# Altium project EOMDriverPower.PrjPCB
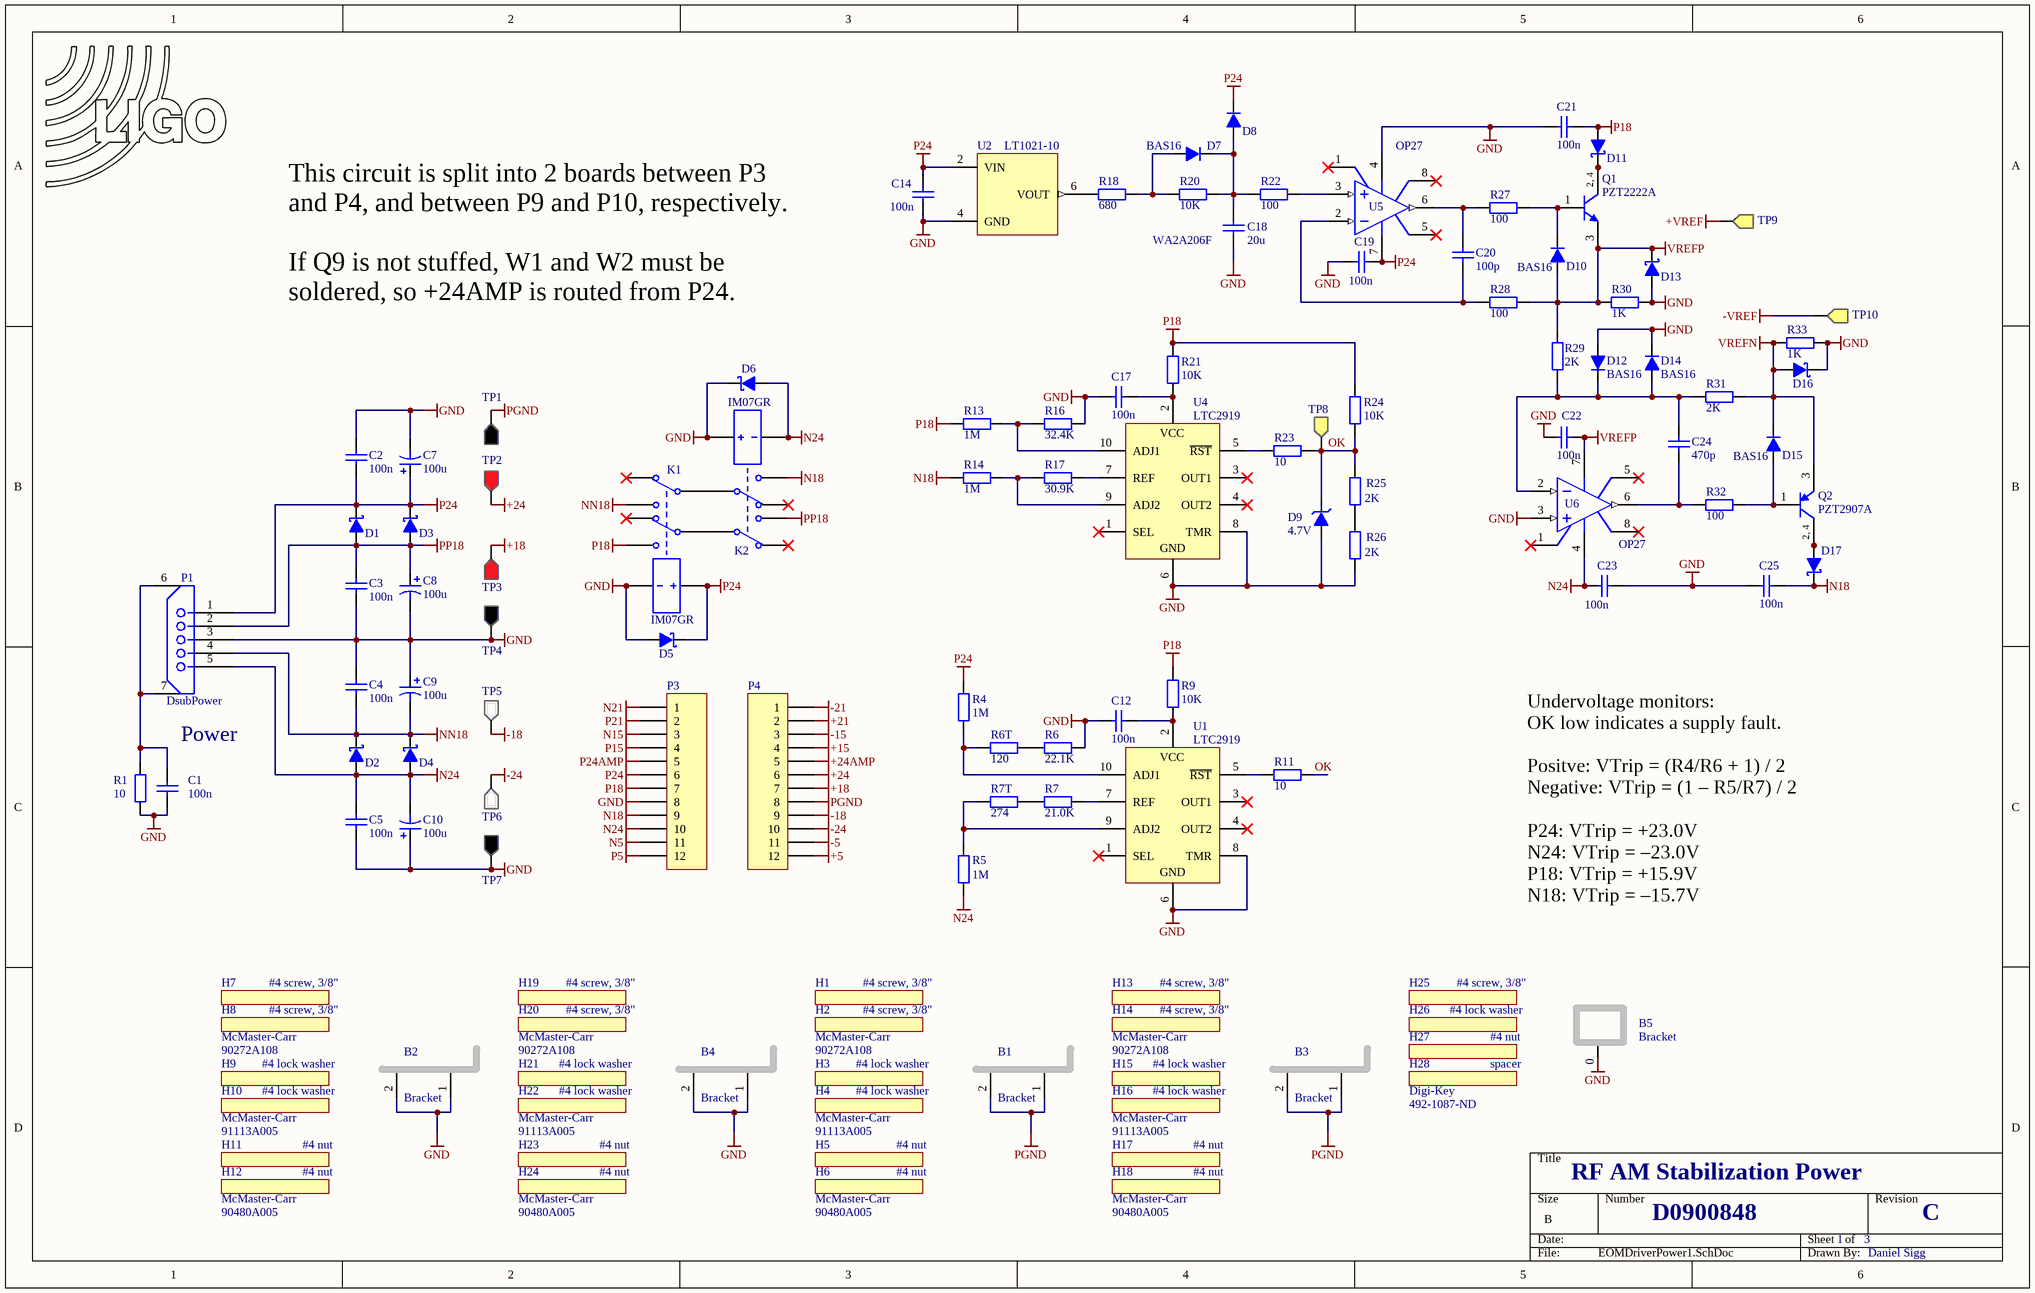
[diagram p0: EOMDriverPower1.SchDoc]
Title: D0900848
3 sheets, 330 parts. Net scope: global (net labels, ports and power ports of the same name join across sheets).
Board file: EOMDriverPower.PcbDoc
Sheets:
  EOMDriverPower1.SchDoc
  EOMDriverPower2.SchDoc
  EOMDriverPower3.SchDoc

## Sheet EOMDriverPower1.SchDoc: D0900848
size B; Engineer: Daniel Sigg; Revision: B; PageSetup: Record=PageOptions¦CenterHorizontal=True¦CenterVertical=True¦PrintScale=1.12¦XCorrection=1.00¦YCorrection=1.00¦PrintKind=0¦BorderSize=5000000¦LeftOffset=0¦BottomOffset=0¦Orientation=2¦PaperLength=1000¦PaperWidth=1000¦Scale=100¦PaperSource=7¦PrintQuality=-3¦MediaType=1¦DitherType=10¦PrintScaleMode=1¦PaperKind=11 x 17¦PaperIndex=121

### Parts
(Parts that share a designator on the sheet are numbered #1, #2 ... from top to bottom, then left to right.)
B1  Bracket  [Bracket-RA_708]
B2  Bracket  [Bracket-RA_708]
B3  Bracket  [Bracket-RA_708]
B4  Bracket  [Bracket-RA_708]
B5  Bracket  [Bracket-RA_7774]  (mechanical)
C1  100n  [CC2013-0805]
C2  100n  [CC2013-0805]
C3  100n  [CC2013-0805]
C4  100n  [CC2013-0805]
C5  100n  [CC2013-0805]
C7  100u  [AC103-041/G]
C8  100u  [AC103-041/G]
C9  100u  [AC103-041/G]
C10  100u  [AC103-041/G]
C12  100n  [CC2013-0805]
C14  100n  [CC2013-0805]
C17  100n  [CC2013-0805]
C18  Part Number: WA2A206F  [CA-ALL8]  (hidden comment: 20u)
C19  100n  [CC2013-0805]
C20  100p  [CC2013-0805]
C21  100n  [CC2013-0805]
C22  100n  [CC2013-0805]
C23  100n  [CC2013-0805]
C24  470p  [CC2013-0805]
C25  100n  [CC2013-0805]
D1  shottky diode  [DO-SMA]  (value not drawn)
D2  shottky diode  [DO-SMA]  (value not drawn)
D3  shottky diode  [DO-SMA]  (value not drawn)
D4  shottky diode  [DO-SMA]  (value not drawn)
D5  shottky diode  [DO-SMA]  (value not drawn)
D6  shottky diode  [DO-SMA]  (value not drawn)
D7  BAS16  [SO-G3/C2.25]
D8  BAS16  [SO-G3/C2.25]  (value not drawn)
D9  Voltage Rating: 4.7V  [DO-SOD123]  (hidden comment: zener diode)
D10  BAS16  [SO-G3/C2.25]
D11  shottky diode  [DO-SMA]  (value not drawn)
D12  BAS16  [SO-G3/C2.25]
D13  shottky diode  [DO-SMA]  (value not drawn)
D14  BAS16  [SO-G3/C2.25]
D15  BAS16  [SO-G3/C2.25]
D16  shottky diode  [DO-SMA]  (value not drawn)
D17  shottky diode  [DO-SMA]  (value not drawn)
H1  #4 screw, 3/8"  (mechanical)
H2  #4 screw, 3/8"  Part Number: 90272A108  Distributor: McMaster-Carr  (mechanical)
H3  #4 lock washer  (mechanical)
H4  #4 lock washer  Part Number: 91113A005  Distributor: McMaster-Carr  (mechanical)
H5  #4 nut  (mechanical)
H6  #4 nut  Part Number: 90480A005  Distributor: McMaster-Carr  (mechanical)
H7  #4 screw, 3/8"  (mechanical)
H8  #4 screw, 3/8"  Part Number: 90272A108  Distributor: McMaster-Carr  (mechanical)
H9  #4 lock washer  (mechanical)
H10  #4 lock washer  Part Number: 91113A005  Distributor: McMaster-Carr  (mechanical)
H11  #4 nut  (mechanical)
H12  #4 nut  Part Number: 90480A005  Distributor: McMaster-Carr  (mechanical)
H13  #4 screw, 3/8"  (mechanical)
H14  #4 screw, 3/8"  Part Number: 90272A108  Distributor: McMaster-Carr  (mechanical)
H15  #4 lock washer  (mechanical)
H16  #4 lock washer  Part Number: 91113A005  Distributor: McMaster-Carr  (mechanical)
H17  #4 nut  (mechanical)
H18  #4 nut  Part Number: 90480A005  Distributor: McMaster-Carr  (mechanical)
H19  #4 screw, 3/8"  (mechanical)
H20  #4 screw, 3/8"  Part Number: 90272A108  Distributor: McMaster-Carr  (mechanical)
H21  #4 lock washer  (mechanical)
H22  #4 lock washer  Part Number: 91113A005  Distributor: McMaster-Carr  (mechanical)
H23  #4 nut  (mechanical)
H24  #4 nut  Part Number: 90480A005  Distributor: McMaster-Carr  (mechanical)
H25  #4 screw, 3/8"  (mechanical)
H26  #4 lock washer  (mechanical)
H27  #4 nut  (mechanical)
H28  spacer  Part Number: 492-1087-ND  Distributor: Digi-Key  (mechanical)
K1  IM07GR  [RELAY_IMG]
K2  IM07GR  [RELAY_IMG]
LOGO1#1  LIGO logo  [LIGO_LOGO]  (value not drawn)  (no BOM)
P1  DsubPower  [DSUB-PWR5-RAPLUG]
P3  TBlock_5.08_12  [TBLOCK-5.08-12]  (value not drawn)
P4  TBlock_5.08_12  [TBLOCK-5.08-12]  (value not drawn)
Q1  PZT2222A  [SOT223]
Q2  PZT2907A  [SOT223]
R1  10  [CR2012-0805]
R4  1M  [CR2012-0805]
R5  1M  [CR2012-0805]
R6  22.1K  [CR2012-0805]
R6T  120  [CR2012-0805]
R7  21.0K  [CR2012-0805]
R7T  274  [CR2012-0805]
R9  10K  [CR2012-0805]
R11  10  [CR2012-0805]
R13  1M  [CR2012-0805]
R14  1M  [CR2012-0805]
R16  32.4K  [CR2012-0805]
R17  30.9K  [CR2012-0805]
R18  680  [CR2012-0805]
R20  10K  [CR2012-0805]
R21  10K  [CR2012-0805]
R22  100  [CR2012-0805]
R23  10  [CR2012-0805]
R24  10K  [CR2012-0805]
R25  2K  [CR2012-0805]
R26  2K  [CR2012-0805]
R27  100  [CR2012-0805]
R28  100  [CR2012-0805]
R29  2K  [CR2012-0805]
R30  1K  [CR2012-0805]
R31  2K  [CR2012-0805]
R32  100  [CR2012-0805]
R33  1K  [CR2012-0805]
TP1  Testpoint  [TP1]  (value not drawn)
TP2  Testpoint  [TP1]  (value not drawn)
TP3  Testpoint  [TP1]  (value not drawn)
TP4  Testpoint  [TP1]  (value not drawn)
TP5  Testpoint  [TP1]  (value not drawn)
TP6  Testpoint  [TP1]  (value not drawn)
TP7  Testpoint  [TP1]  (value not drawn)
TP8  Testpoint  [TP1]  (value not drawn)
TP9  Testpoint  [TP1]  (value not drawn)
TP10  Testpoint  [TP1]  (value not drawn)
U1  LTC2919  [MSOP10]
U2  LT1021-10  [DIP-8]
U4  LTC2919  [MSOP10]
U5  OP27  [SO-G8]
U6  OP27  [SO-G8]

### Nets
+5: P4.12
+15: P4.4
+18: P4.7 TP3.1
+21: P4.2
+24: P4.6 TP2.1
+24AMP: P4.5
+VREF: TP9.1
-5: P4.11
-15: P4.3
-18: P4.9 TP5.1
-21: P4.1
-24: P4.10 TP6.1
-VREF: TP10.1
GND: B2.1(GND) B2.2(GND) B4.1(GND) B4.2(GND) C1.2 C2.1 C3.1 C4.2 C5.2 C7.2 C8.2 C9.1 C10.1 C12.1 C14.1 C17.1 C18.2 C19.1 C21.2 C22.2 C23.1 C25.2 D5.1(A) D6.2(K) D9.1(A) D12.1(A) D13.1(A) D14.3(K) D16.2(K) K1.8(COIL2) K2.7(COIL1) P1.3(A3) P3.8 R1.2 R6.1 R16.1 R26.1 R30.2 R33.2 TP4.1 TP7.1 U1.6(GND) U1.8(TMR) U2.4(GND) U4.6(GND) U4.8(TMR) U5.4(V-) U6.3(IN+)
N5: P3.11
N15: P3.3
N18: C25.1 D17.2(K) K2.6(2NO) P3.9 R14.2
N21: P3.1
N24: C5.1 C10.2 C23.2 D2.1(A) D4.1(A) D6.1(A) K2.8(COIL2) P1.5(A5) P3.10 R5.2 U6.4(V-)
NN18: C4.1 C9.2 D2.2(K) D4.2(K) K1.3(1NO) P1.4(A4)
P5: P3.12
P15: P3.4
P18: C21.1 D11.1(A) K1.6(2NO) P3.7 R9.2 R13.2 R21.2 R24.2
P21: P3.2
P24: C2.2 C7.1 C14.2 C19.2 D1.2(K) D3.2(K) D5.2(K) D8.3(K) K1.7(COIL1) P1.1(A1) P3.6 R4.1 U2.2(VIN) U5.7(V+)
P24AMP: P3.5
PGND: B1.1(GND) B1.2(GND) B3.1(GND) B3.2(GND) P4.8 TP1.1
PP18: C3.2 C8.1 D1.1(A) D3.1(A) K2.3(1NO) P1.2(A2)
VREFN: D15.3(K) D16.1(A) Q2.3(E) R31.2 R33.1
VREFP: C22.1 D10.1(A) D13.2(K) Q1.3(E) R28.2 R29.1 R30.1 U6.7(V+)
OK: D9.2(K) R11.2 R23.2 R24.1 R25.2 TP8.1
NetC1_1: C1.1 P1.6(A6) P1.7(A7) R1.1
NetC12_2: C12.2 R9.1 U1.2(VCC)
NetC17_2: C17.2 R21.1 U4.2(VCC)
NetC18_1: C18.1 D7.3(K) D8.1(A) R20.2 R22.1
NetC20_1: C20.1 R28.1 U5.2(IN-)
NetC20_2: C20.2 R27.1 U5.6(OUT)
NetC24_1: C24.1 R32.2 U6.6(OUT)
NetC24_2: C24.2 D12.3(K) D14.1(A) R29.2 R31.1 U6.2(IN-)
NetD7_1: D7.1(A) R18.2 R20.1
NetD10_3: D10.3(K) Q1.1(B) R27.2
NetD11_2: D11.2(K) Q1.2(C) Q1.4(C)
NetD15_1: D15.1(A) Q2.1(B) R32.1
NetD17_1: D17.1(A) Q2.2(C) Q2.4(C)
NetK1_1: K1.1(1COM) K2.4(2COM)
NetK1_4: K1.4(2COM) K2.1(1COM)
NetR4_2: R4.2 R6T.2 U1.10(ADJ1)
NetR5_1: R5.1 R7T.2 U1.9(ADJ2)
NetR6_2: R6.2 R6T.1
NetR7_1: R7.1 U1.7(REF)
NetR7_2: R7.2 R7T.1
NetR11_1: R11.1 U1.5(~{RST})
NetR13_1: R13.1 R16.2 U4.10(ADJ1)
NetR14_1: R14.1 R17.2 U4.9(ADJ2)
NetR17_1: R17.1 U4.7(REF)
NetR18_1: R18.1 U2.6(VOUT)
NetR22_2: R22.2 U5.3(IN+)
NetR23_1: R23.1 U4.5(~{RST})
NetR25_1: R25.1 R26.2

Not connected (* = marked no-connect by the designer): B5 0(GND); D7 2; D8 2; D10 2; D12 2; D14 2; D15 2; K1 2(1NC)* 5(2NC)*; K2 2(1NC)* 5(2NC)*; U1 1(SEL)* 3(OUT1)* 4(OUT2)*; U2 1(DNC) 3(DNC) 5(DNC) 7(DNC) 8(DNC); U4 1(SEL)* 3(OUT1)* 4(OUT2)*; U5 1(CMPEN)* 5(NC)* 8(CMPEN)*; U6 1(CMPEN)* 5(NC)* 8(CMPEN)*

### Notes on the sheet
- This circuit is split into 2 boards between P3
  and P4, and between P9 and P10, respectively.
  If Q9 is not stuffed, W1 and W2 must be
  soldered, so +24AMP is routed from P24.
- Power
- Undervoltage monitors:
  OK low indicates a supply fault.
  Positve: VTrip = (R4/R6 + 1) / 2
  Negative: VTrip = (1 – R5/R7) / 2
  P24: VTrip = +23.0V
  N24: VTrip = –23.0V
  P18: VTrip = +15.9V
  N18: VTrip = –15.7V
- RF AM Stabilization Power
- D0900848
- 1
- 3
- C
- Daniel Sigg
- Labels drawn without touching a wire or pin: GND

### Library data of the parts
B1-B4 = Bracket_708: Keystone Electronics right-angle 6-32 steel, 708; Part Number: 708K-ND
B5 = Bracket_7774: Keystone Electronics right-angle 4-40 steel, 616; Part Number: 616K-ND
C1-C5 C12 C14 C17 C19 C21-C23 C25 = ChipCap: Capacitor, surface mount; Part Number: 311-1140-1-ND; Tolerance: 10%
C7-C10 = ChipElectrolyte: Electrolyte capacitor, surface mount; Part Number: PCE3819CT-ND; Tolerance: 20%; Voltage Rating: 63V
C18 = CapFilmAxial: Film Capacitor, axial lead; Tolerance: 1%; Voltage Rating: 50V
C20 = ChipCap: Capacitor, surface mount; Part Number: 311-1111-1-ND; Tolerance: 10%
C24 = ChipCap: Capacitor, surface mount; Part Number: 311-1119-1-ND; Tolerance: 10%
D1-D4 D11 D13 D16 D17 = DIODE_SHOTTKY: Single shottky diode; Part Number: 641-1258-1-ND; Voltage Rating: 40V
D5 D6 = DIODE_SHOTTKY: Single shottky diode; Part Number: 641-1258-1-ND
D7 D8 D10 D12 D14 D15 = DIODE_SOT23: Single diode in SOT23 package; Part Number: BAS16FSCT-ND
D9 = DIODE_ZENER: Single zener diode; Part Number: MMSZ5230B-FDICT-ND
H1 H7 H13 H19 H25 = Partlist: Mounting hardware; Part Number: 90272A108
H2 H4 H6 H8 H10 H12 H14 H16 H18 H20 H22 H24 = Partlist: Mounting hardware
H3 H9 H15 H21 H26 = Partlist: Mounting hardware; Part Number: 91113A005
H5 H11 H17 H23 H27 = Partlist: Mounting hardware; Part Number: 90480A005
H28 = Partlist: Spacer, 0.125", #4
K1 K2 = Relay_DPDT: Dual-pole dual-throw relay; Part Number: PB1090CT-ND; Coil Voltage: 24V; Current Rating: 2A
LOGO1#1 = LIGO_logo
P1 = DSUB_PWR_5PIN: 5 contact Dsub Power Connector; Part Number: 609-2834-ND
P3 = TBlock_5.08_12: Terminal block, 5.08mm, 12-Pin; Part Number: 281-1285-ND
P4 = TBlock_5.08_12: Terminal block, 5.08mm, 12-Pin; Part Number: NL
Q1 = PZTA42: NPN General Purpose Transistor; Part Number: PZT2222ACT-ND
Q2 = BCP51: PNP Medium Power Transistor; Part Number: PZT2907AT1GOSCT-ND
R1 R11 R23 = ChipRes1: Resistor, surface mount; Part Number: A103143CT-ND; Tolerance: 0.1%
R4 R5 R13 R14 = ChipRes1: Resistor, surface mount; Part Number: P1MDACT-ND; Tolerance: 0.1%
R6 = ChipRes1: Resistor, surface mount; Part Number: P22.1KDACT-ND; Tolerance: 0.1%
R6T = ChipRes1: Resistor, surface mount; Part Number: P120DACT-ND; Tolerance: 0.1%
R7 = ChipRes1: Resistor, surface mount; Part Number: P21KDACT-ND; Tolerance: 0.1%
R7T = ChipRes1: Resistor, surface mount; Part Number: P274DACT-ND; Tolerance: 0.1%
R9 R20 R21 R24 = ChipRes1: Resistor, surface mount; Part Number: P10KDACT-ND; Tolerance: 0.1%
R16 = ChipRes1: Resistor, surface mount; Part Number: P32.4KDACT-ND; Tolerance: 0.1%
R17 = ChipRes1: Resistor, surface mount; Part Number: P30.9KDACT-ND; Tolerance: 0.1%
R18 = ChipRes1: Resistor, surface mount; Part Number: P680DACT-ND; Tolerance: 0.1%
R22 R27 R28 R32 = ChipRes1: Resistor, surface mount; Part Number: P100DACT-ND; Tolerance: 0.1%
R25 R26 R29 R31 = ChipRes1: Resistor, surface mount; Part Number: P2.0KDACT-ND; Tolerance: 0.1%
R30 R33 = ChipRes1: Resistor, surface mount; Part Number: P1.0KDACT-ND; Tolerance: 0.1%
TP1 TP4 TP7 = TP_GND: Testpoint, black; Part Number: 5006K-ND
TP2 TP3 = TP_POSITIVE: Testpoint, red; Part Number: 5005K-ND
TP5 TP6 = TP_NEGATIVE: Testpoint, white; Part Number: 5007K-ND
TP8-TP10 = TP_SIGNAL: Testpoint, yellow; Part Number: 5009K-ND
U1 U4 = LTC2919: Precision Triple/Dual Input UV, OV and Negative Voltage Monitor; Part Number: LTC2919CMS-5#PBF-ND
U2 = LT1021-7: Voltage Ref; Part Number: LT1021BCN8-10#PBF
U5 U6 = OP27GS: Low-Noise, Precision Operational Amplifier; Part Number: OP27GSZ-ND

## Sheet EOMDriverPower2.SchDoc: D0900848
size B
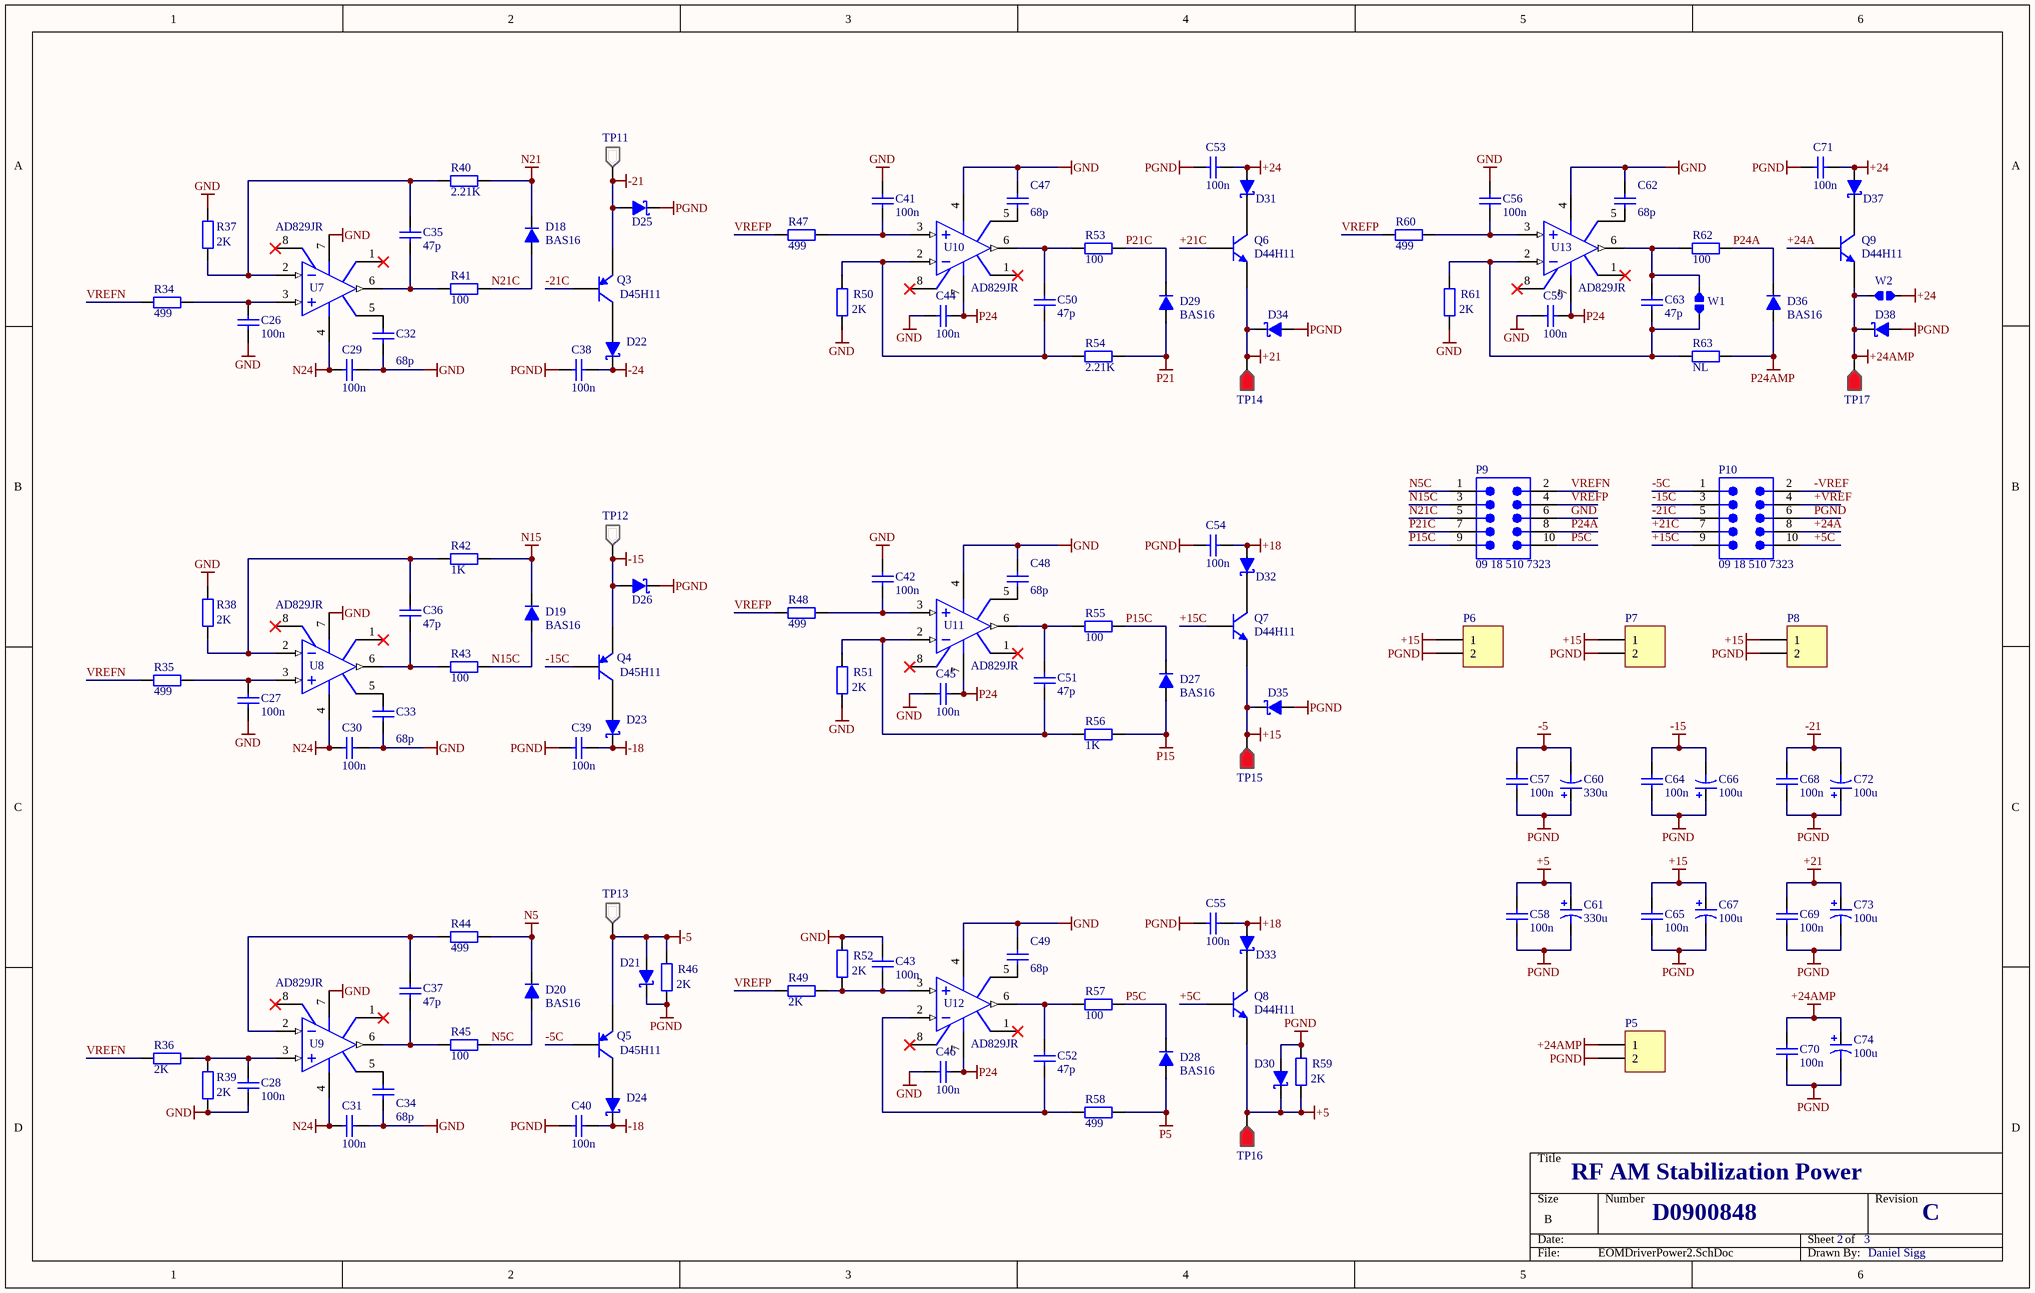
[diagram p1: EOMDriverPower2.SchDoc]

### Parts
C26  100n  [CC2013-0805]
C27  100n  [CC2013-0805]
C28  100n  [CC2013-0805]
C29  100n  [CC2013-0805]
C30  100n  [CC2013-0805]
C31  100n  [CC2013-0805]
C32  68p  [CC2013-0805]
C33  68p  [CC2013-0805]
C34  68p  [CC2013-0805]
C35  47p  [CC2013-0805]
C36  47p  [CC2013-0805]
C37  47p  [CC2013-0805]
C38  100n  [CC2013-0805]
C39  100n  [CC2013-0805]
C40  100n  [CC2013-0805]
C41  100n  [CC2013-0805]
C42  100n  [CC2013-0805]
C43  100n  [CC2013-0805]
C44  100n  [CC2013-0805]
C45  100n  [CC2013-0805]
C46  100n  [CC2013-0805]
C47  68p  [CC2013-0805]
C48  68p  [CC2013-0805]
C49  68p  [CC2013-0805]
C50  47p  [CC2013-0805]
C51  47p  [CC2013-0805]
C52  47p  [CC2013-0805]
C53  100n  [CC2013-0805]
C54  100n  [CC2013-0805]
C55  100n  [CC2013-0805]
C56  100n  [CC2013-0805]
C57  100n  [CC2013-0805]
C58  100n  [CC2013-0805]
C59  100n  [CC2013-0805]
C60  330u  [AC083-033/F]
C61  330u  [AC083-033/F]
C62  68p  [CC2013-0805]
C63  47p  [CC2013-0805]
C64  100n  [CC2013-0805]
C65  100n  [CC2013-0805]
C66  100u  [AC083-033/F]
C67  100u  [AC083-033/F]
C68  100n  [CC2013-0805]
C69  100n  [CC2013-0805]
C70  100n  [CC2013-0805]
C71  100n  [CC2013-0805]
C72  100u  [AC083-033/F]
C73  100u  [AC083-033/F]
C74  100u  [AC083-033/F]
D18  BAS16  [SO-G3/C2.25]
D19  BAS16  [SO-G3/C2.25]
D20  BAS16  [SO-G3/C2.25]
D21  shottky diode  [DO-SMA]  (value not drawn)
D22  shottky diode  [DO-SMA]  (value not drawn)
D23  shottky diode  [DO-SMA]  (value not drawn)
D24  shottky diode  [DO-SMA]  (value not drawn)
D25  shottky diode  [DO-SMA]  (value not drawn)
D26  shottky diode  [DO-SMA]  (value not drawn)
D27  BAS16  [SO-G3/C2.25]
D28  BAS16  [SO-G3/C2.25]
D29  BAS16  [SO-G3/C2.25]
D30  shottky diode  [DO-SMA]  (value not drawn)
D31  shottky diode  [DO-SMA]  (value not drawn)
D32  shottky diode  [DO-SMA]  (value not drawn)
D33  shottky diode  [DO-SMA]  (value not drawn)
D34  shottky diode  [DO-SMA]  (value not drawn)
D35  shottky diode  [DO-SMA]  (value not drawn)
D36  BAS16  [SO-G3/C2.25]
D37  shottky diode  [DO-SMA]  (value not drawn)
D38  shottky diode  [DO-SMA]  (value not drawn)
P5  TBlock_5.08_2  [TBLOCK-5.08-2]  (value not drawn)
P6  TBlock_5.08_2  [TBLOCK-5.08-2]  (value not drawn)
P7  TBlock_5.08_2  [TBLOCK-5.08-2]  (value not drawn)
P8  TBlock_5.08_2  [TBLOCK-5.08-2]  (value not drawn)
P9  09 18 510 7323  [918510x323]
P10  09 18 510 7323  [918510x324]
Q3  D45H11  [TO-220V]
Q4  D45H11  [TO-220V]
Q5  D45H11  [TO-220V]
Q6  D44H11  [TO-220V]
Q7  D44H11  [TO-220V]
Q8  D44H11  [TO-220V]
Q9  D44H11  [TO-220V]
R34  499  [CR2012-0805]
R35  499  [CR2012-0805]
R36  2K  [CR2012-0805]
R37  2K  [CR2012-0805]
R38  2K  [CR2012-0805]
R39  2K  [CR2012-0805]
R40  2.21K  [CR2012-0805]
R41  100  [CR2012-0805]
R42  1K  [CR2012-0805]
R43  100  [CR2012-0805]
R44  499  [CR2012-0805]
R45  100  [CR2012-0805]
R46  2K  [CR2012-0805]
R47  499  [CR2012-0805]
R48  499  [CR2012-0805]
R49  2K  [CR2012-0805]
R50  2K  [CR2012-0805]
R51  2K  [CR2012-0805]
R52  2K  [CR2012-0805]
R53  100  [CR2012-0805]
R54  2.21K  [CR2012-0805]
R55  100  [CR2012-0805]
R56  1K  [CR2012-0805]
R57  100  [CR2012-0805]
R58  499  [CR2012-0805]
R59  2K  [CR2012-0805]
R60  499  [CR2012-0805]
R61  2K  [CR2012-0805]
R62  100  [CR2012-0805]
R63  NL  [CR2012-0805]
TP11  Testpoint  [TP1]  (value not drawn)
TP12  Testpoint  [TP1]  (value not drawn)
TP13  Testpoint  [TP1]  (value not drawn)
TP14  Testpoint  [TP1]  (value not drawn)
TP15  Testpoint  [TP1]  (value not drawn)
TP16  Testpoint  [TP1]  (value not drawn)
TP17  Testpoint  [TP1]  (value not drawn)
U7  AD829JR  [SO-G8]
U8  AD829JR  [SO-G8]
U9  AD829JR  [SO-G8]
U10  AD829JR  [SO-G8]
U11  AD829JR  [SO-G8]
U12  AD829JR  [SO-G8]
U13  AD829JR  [SO-G8]
W1  Jumper  [JR2013-0805]  (value not drawn)  (no BOM)
W2  Jumper  [JR2013-0805]  (value not drawn)  (no BOM)

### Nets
+5: C58.2 C61.1 D30.2(K) Q8.3(E) R59.1 TP16.1
+15: C65.2 C67.1 D35.2(K) P6.1 P7.1 P8.1 Q7.3(E) TP15.1
+18: C54.1 C55.1 D32.1(A) D33.1(A)
+21: C69.2 C73.1 D34.2(K) Q6.3(E) TP14.1
+24: C53.1 C71.1 D31.1(A) D37.1(A) W2.1
+24AMP: C70.2 C74.1 D38.2(K) P5.1 Q9.3(E) TP17.1 W2.2
+VREF: P10.4
-5: C57.1 C60.2 D21.1(A) Q5.3(E) R46.2 TP13.1
-15: C64.1 C66.2 D26.1(A) Q4.3(E) TP12.1
-18: C39.1 C40.1 D23.2(K) D24.2(K)
-21: C68.1 C72.2 D25.1(A) Q3.3(E) TP11.1
-24: C38.1 D22.2(K)
-VREF: P10.2
GND: C26.1 C27.1 C28.1 C29.1 C30.1 C31.1 C32.1 C33.1 C34.1 C41.2 C42.2 C43.2 C44.2 C45.2 C46.2 C47.2 C48.2 C49.2 C56.2 C59.2 C62.2 P9.6 R37.1 R38.1 R39.2 R50.1 R51.1 R52.2 R61.1 U7.7(V+) U8.7(V+) U9.7(V+) U10.4(V-) U11.4(V-) U12.4(V-) U13.4(V-)
N5: D20.3(K) R44.1
N15: D19.3(K) R42.1
N21: D18.3(K) R40.1
N24: C29.2 C30.2 C31.2 U7.4(V-) U8.4(V-) U9.4(V-)
P5: D28.1(A) R58.2
P15: D27.1(A) R56.2
P21: D29.1(A) R54.2
P24: C44.1 C45.1 C46.1 C59.1 U10.7(V+) U11.7(V+) U12.7(V+) U13.7(V+)
P24AMP: D36.1(A) R63.2
PGND: C38.2 C39.2 C40.2 C53.2 C54.2 C55.2 C57.2 C58.1 C60.1 C61.2 C64.2 C65.1 C66.1 C67.2 C68.2 C69.1 C70.1 C71.2 C72.1 C73.2 C74.2 D21.2(K) D25.2(K) D26.2(K) D30.1(A) D34.1(A) D35.1(A) D38.1(A) P5.2 P6.2 P7.2 P8.2 P10.6 R46.1 R59.2
VREFN: P9.2 R34.1 R35.1 R36.1
VREFP: P9.4 R47.1 R48.1 R49.1 R60.1
+5C: P10.10 Q8.1(B)
+15C: P10.9 Q7.1(B)
+21C: P10.7 Q6.1(B)
+24A: P10.8 Q9.1(B)
-5C: P10.1 Q5.1(B)
-15C: P10.3 Q4.1(B)
-21C: P10.5 Q3.1(B)
N5C: D20.1(A) P9.1 R45.1
N15C: D19.1(A) P9.3 R43.1
N21C: D18.1(A) P9.5 R41.1
P5C: D28.3(K) P9.10 R57.2
P15C: D27.3(K) P9.9 R55.2
P21C: D29.3(K) P9.7 R53.2
P24A: D36.3(K) P9.8 R62.2
NetC26_2: C26.2 R34.2 U7.3(IN+)
NetC27_2: C27.2 R35.2 U8.3(IN+)
NetC28_2: C28.2 R36.2 R39.1 U9.3(IN+)
NetC32_2: C32.2 U7.5(C_COMP)
NetC33_2: C33.2 U8.5(C_COMP)
NetC34_2: C34.2 U9.5(C_COMP)
NetC35_1: C35.1 R41.2 U7.6(OUT)
NetC35_2: C35.2 R37.2 R40.2 U7.2(IN-)
NetC36_1: C36.1 R43.2 U8.6(OUT)
NetC36_2: C36.2 R38.2 R42.2 U8.2(IN-)
NetC37_1: C37.1 R45.2 U9.6(OUT)
NetC37_2: C37.2 R44.2 U9.2(IN-)
NetC41_1: C41.1 R47.2 U10.3(IN+)
NetC42_1: C42.1 R48.2 U11.3(IN+)
NetC43_1: C43.1 R49.2 R52.1 U12.3(IN+)
NetC47_1: C47.1 U10.5(C_COMP)
NetC48_1: C48.1 U11.5(C_COMP)
NetC49_1: C49.1 U12.5(C_COMP)
NetC50_1: C50.1 R50.2 R54.1 U10.2(IN-)
NetC50_2: C50.2 R53.1 U10.6(OUT)
NetC51_1: C51.1 R51.2 R56.1 U11.2(IN-)
NetC51_2: C51.2 R55.1 U11.6(OUT)
NetC52_1: C52.1 R58.1 U12.2(IN-)
NetC52_2: C52.2 R57.1 U12.6(OUT)
NetC56_1: C56.1 R60.2 U13.3(IN+)
NetC62_1: C62.1 U13.5(C_COMP)
NetC63_1: C63.1 R61.2 R63.1 U13.2(IN-) W1.1
NetC63_2: C63.2 R62.1 U13.6(OUT) W1.2
NetD22_1: D22.1(A) Q3.2(C)
NetD23_1: D23.1(A) Q4.2(C)
NetD24_1: D24.1(A) Q5.2(C)
NetD31_2: D31.2(K) Q6.2(C)
NetD32_2: D32.2(K) Q7.2(C)
NetD33_2: D33.2(K) Q8.2(C)
NetD37_2: D37.2(K) Q9.2(C)

Not connected (* = marked no-connect by the designer): D18 2; D19 2; D20 2; D27 2; D28 2; D29 2; D36 2; U7 1(OS_NUL)* 8(OS_NUL)*; U8 1(OS_NUL)* 8(OS_NUL)*; U9 1(OS_NUL)* 8(OS_NUL)*; U10 1(OS_NUL)* 8(OS_NUL)*; U11 1(OS_NUL)* 8(OS_NUL)*; U12 1(OS_NUL)* 8(OS_NUL)*; U13 1(OS_NUL)* 8(OS_NUL)*

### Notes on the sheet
- RF AM Stabilization Power
- D0900848
- 2
- 3
- C
- Daniel Sigg

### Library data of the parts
C26-C31 C38-C46 C53-C59 C64 C65 C68-C71 = ChipCap: as C1 on sheet EOMDriverPower1
C32-C34 C47-C49 C62 = ChipCap: Capacitor, surface mount; Part Number: 311-1109-1-ND; Tolerance: 10%
C35-C37 C50-C52 C63 = ChipCap: Capacitor, surface mount; Part Number: 311-1107-1-ND; Tolerance: 10%
C60 C61 = ChipElectrolyte: Electrolyte capacitor, surface mount; Part Number: 493-2251-1-ND; Tolerance: 20%; Voltage Rating: 10V
C66 C67 C72-C74 = ChipElectrolyte: Electrolyte capacitor, surface mount; Part Number: 493-2306-1-ND; Tolerance: 20%; Voltage Rating: 50V
D18-D20 D27-D29 D36 = DIODE_SOT23: as D7 on sheet EOMDriverPower1
D21-D26 D30-D35 D37 D38 = DIODE_SHOTTKY: as D1 on sheet EOMDriverPower1
P5-P8 = TBlock_5.08_2: Terminal block, 5.08mm, 2-Pin; Part Number: 281-1297-ND
P9 = 09 18 510 7323: Flat Cable Connector (IDC), Low-Profile Male Header, Angled Solder Pin, 10 Contacts, Performance Level 3; Part Number: A31192-ND
P10 = 09 18 510 7323: Flat Cable Connector (IDC), Low-Profile Male Header, Angled Solder Pin, 10 Contacts, Performance Level 3; Part Number: A31183-ND
Q3-Q5 = D45H8: PNP Power Amplifier; Part Number: 497-2578-5-ND
Q6-Q8 = D44H8: NPN Power Amplifier; Part Number: 497-2616-5-ND
Q9 = D44H8: NPN Power Amplifier
R34 R35 R44 R47 R48 R58 R60 = ChipRes1: Resistor, surface mount; Part Number: P499DACT-ND; Tolerance: 0.1%
R36-R39 R46 R49-R52 R59 R61 = ChipRes1: as R25 on sheet EOMDriverPower1
R40 R54 = ChipRes1: Resistor, surface mount; Part Number: P2.21KDACT-ND; Tolerance: 0.1%
R41 R43 R45 R53 R55 R57 R62 = ChipRes1: as R22 on sheet EOMDriverPower1
R42 R56 = ChipRes1: as R30 on sheet EOMDriverPower1
R63 = ChipRes1: Resistor, surface mount; Tolerance: 0.1%
TP11-TP13 = TP_NEGATIVE: Testpoint, white; Part Number: 5007K-ND
TP14-TP17 = TP_POSITIVE: Testpoint, red; Part Number: 5005K-ND
U7-U13 = AD829JR: High-Speed, Low-Noise Video Operational Amplifier; Part Number: AD829JRZ-ND
W1 W2 = Jumper: Jumper Pad

## Sheet EOMDriverPower3.SchDoc: D0900848
size B; Engineer: Daniel Sigg; Revision: B; PageSetup: Record=PageOptions¦CenterHorizontal=True¦CenterVertical=True¦PrintScale=1.12¦XCorrection=1.00¦YCorrection=1.00¦PrintKind=0¦BorderSize=5000000¦LeftOffset=0¦BottomOffset=0¦Orientation=2¦PaperLength=1000¦PaperWidth=1000¦Scale=100¦PaperSource=7¦PrintQuality=-3¦MediaType=1¦DitherType=10¦PrintScaleMode=1¦PaperKind=11 x 17¦PaperIndex=119
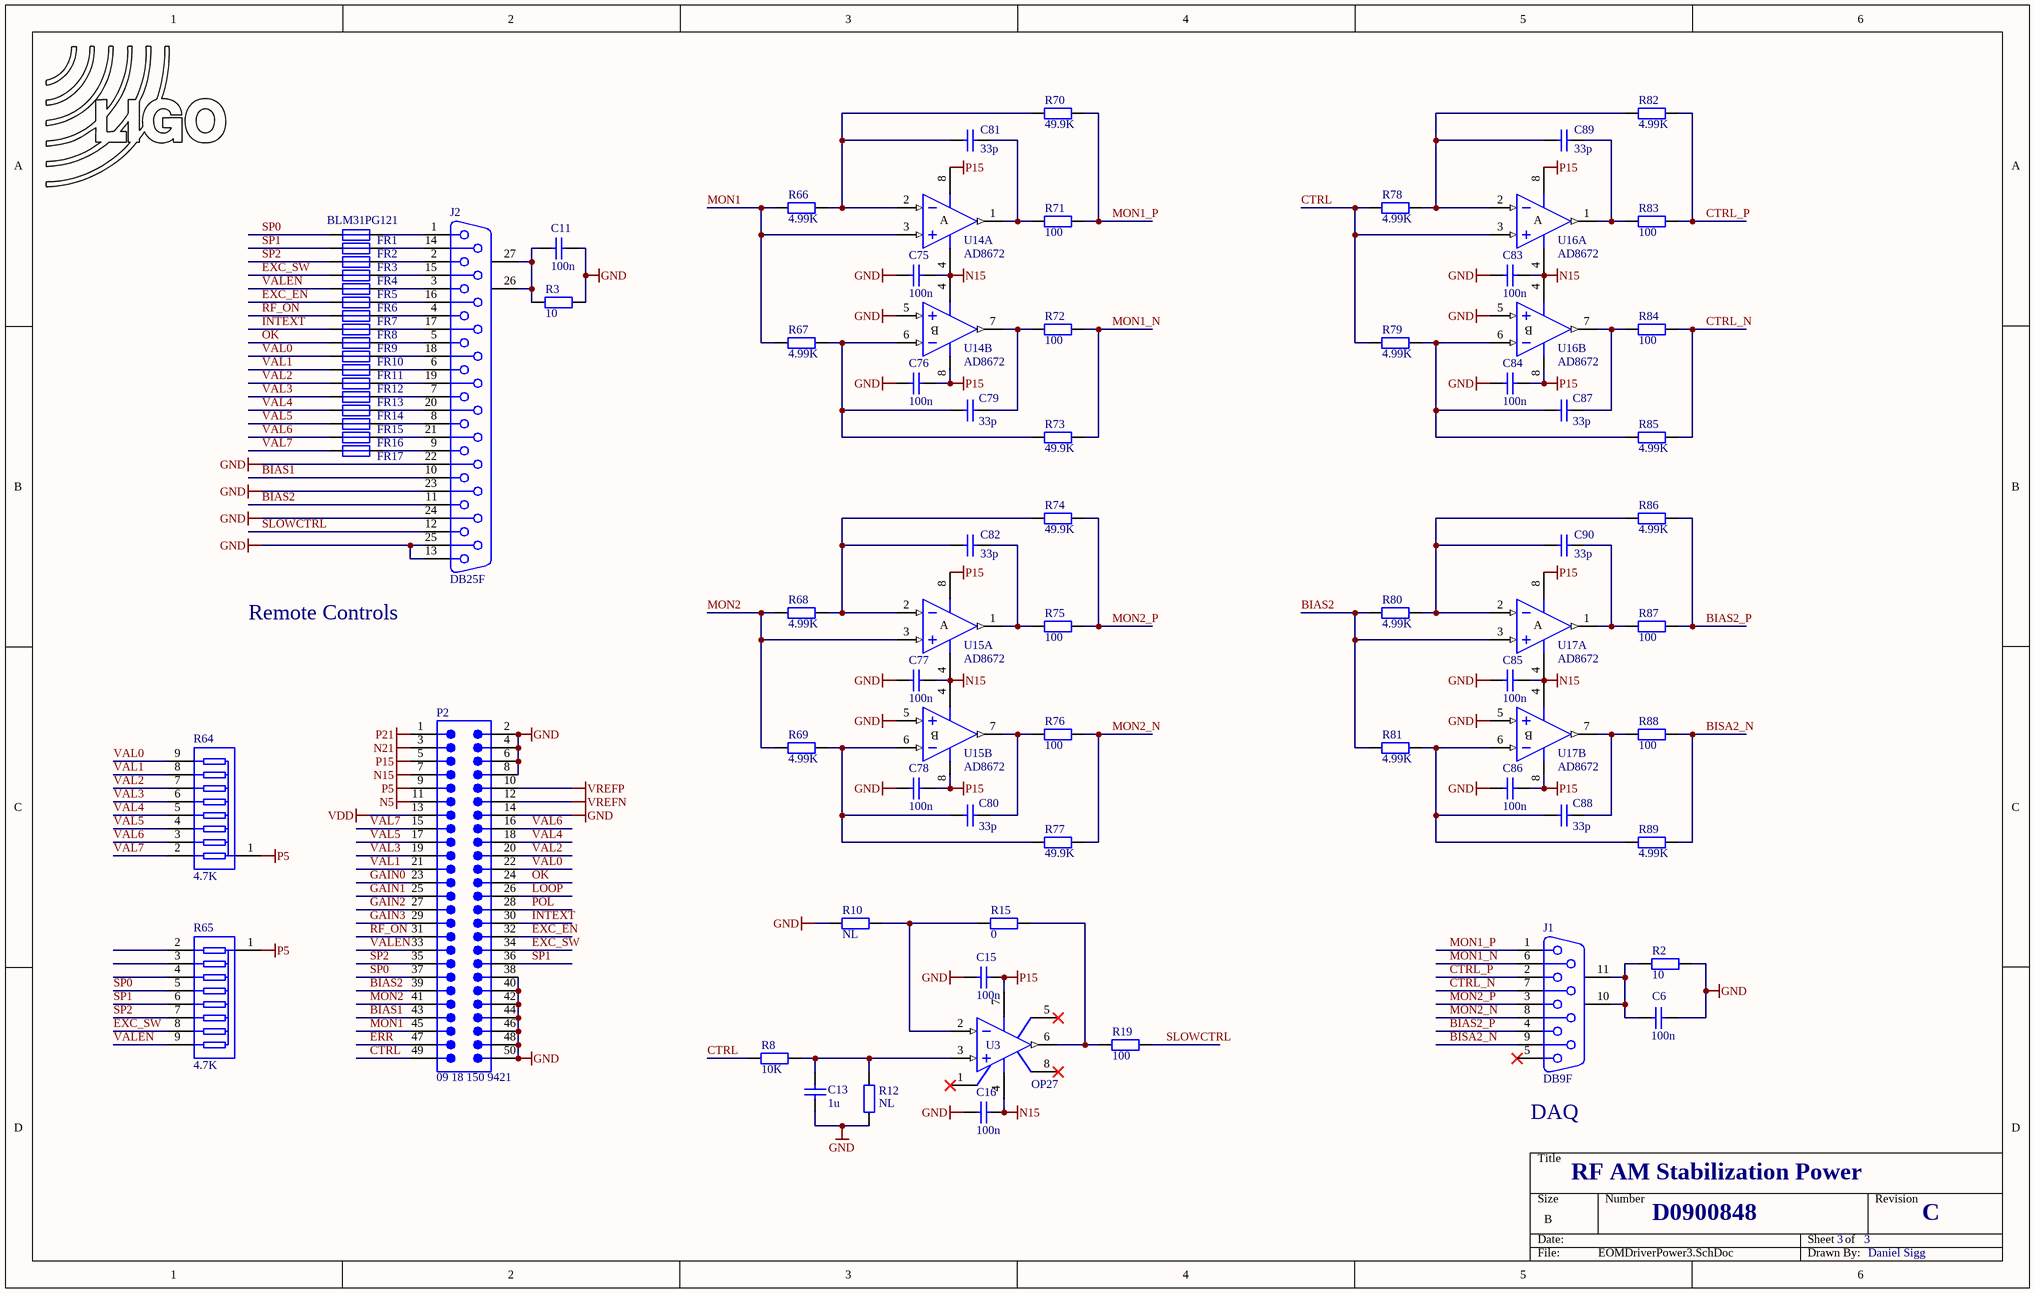
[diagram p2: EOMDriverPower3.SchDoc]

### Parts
(Parts that share a designator on the sheet are numbered #1, #2 ... from top to bottom, then left to right.)
C6  100n  [CC2013-0805]
C11  100n  [CC2013-0805]
C13  1u  [CA-ALL4]
C15  100n  [CC2013-0805]
C16  100n  [CC2013-0805]
C75  100n  [CC2013-0805]
C76  100n  [CC2013-0805]
C77  100n  [CC2013-0805]
C78  100n  [CC2013-0805]
C79  33p  [CC2013-0805]
C80  33p  [CC2013-0805]
C81  33p  [CC2013-0805]
C82  33p  [CC2013-0805]
C83  100n  [CC2013-0805]
C84  100n  [CC2013-0805]
C85  100n  [CC2013-0805]
C86  100n  [CC2013-0805]
C87  33p  [CC2013-0805]
C88  33p  [CC2013-0805]
C89  33p  [CC2013-0805]
C90  33p  [CC2013-0805]
FR1  BLM31PG121  [CC3216-1206]
FR2  BLM31PG121  [CC3216-1206]  (value not drawn)
FR3  BLM31PG121  [CC3216-1206]  (value not drawn)
FR4  BLM31PG121  [CC3216-1206]  (value not drawn)
FR5  BLM31PG121  [CC3216-1206]  (value not drawn)
FR6  BLM31PG121  [CC3216-1206]  (value not drawn)
FR7  BLM31PG121  [CC3216-1206]  (value not drawn)
FR8  BLM31PG121  [CC3216-1206]  (value not drawn)
FR9  BLM31PG121  [CC3216-1206]  (value not drawn)
FR10  BLM31PG121  [CC3216-1206]  (value not drawn)
FR11  BLM31PG121  [CC3216-1206]  (value not drawn)
FR12  BLM31PG121  [CC3216-1206]  (value not drawn)
FR13  BLM31PG121  [CC3216-1206]  (value not drawn)
FR14  BLM31PG121  [CC3216-1206]  (value not drawn)
FR15  BLM31PG121  [CC3216-1206]  (value not drawn)
FR16  BLM31PG121  [CC3216-1206]  (value not drawn)
FR17  BLM31PG121  [CC3216-1206]  (value not drawn)
J1  DB9F  [DB9F-RA]
J2  DB25F  [DB25F-RA]
LOGO1#2  LIGO logo  [LIGO_LOGO]  (value not drawn)  (graphical)
P2  09 18 150 9421  [918550x323]
R2  10  [CR2012-0805]
R3  10  [CR2012-0805]
R8  10K  [CR2012-0805]
R10  NL  [CR2012-0805]
R12  NL  [CR2012-0805]
R15  0  [CR2012-0805]
R19  100  [CR2012-0805]
R64  value 4.7K  [RES9-1.27ROW]  (hidden comment: Resistor array)
R65  value 4.7K  [RES9-1.27ROW]  (hidden comment: Resistor array)
R66  4.99K  [CR2012-0805]
R67  4.99K  [CR2012-0805]
R68  4.99K  [CR2012-0805]
R69  4.99K  [CR2012-0805]
R70  49.9K  [CR2012-0805]
R71  100  [CR2012-0805]
R72  100  [CR2012-0805]
R73  49.9K  [CR2012-0805]
R74  49.9K  [CR2012-0805]
R75  100  [CR2012-0805]
R76  100  [CR2012-0805]
R77  49.9K  [CR2012-0805]
R78  4.99K  [CR2012-0805]
R79  4.99K  [CR2012-0805]
R80  4.99K  [CR2012-0805]
R81  4.99K  [CR2012-0805]
R82  4.99K  [CR2012-0805]
R83  100  [CR2012-0805]
R84  100  [CR2012-0805]
R85  4.99K  [CR2012-0805]
R86  4.99K  [CR2012-0805]
R87  100  [CR2012-0805]
R88  100  [CR2012-0805]
R89  4.99K  [CR2012-0805]
U3  OP27  [SO-G8]
U14  AD8672  [SO-8_N]  (parts A,B of 2)
U15  AD8672  [SO-8_N]  (parts A,B of 2)
U16  AD8672  [SO-8_N]  (parts A,B of 2)
U17  AD8672  [SO-8_N]  (parts A,B of 2)

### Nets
GND: C6.1 C11.2 C13.2 C15.1 C16.1 C75.2 C76.2 C77.2 C78.2 C83.2 C84.2 C85.2 C86.2 J2.13 J2.22 J2.23 J2.24 J2.25 P2.2 P2.4 P2.6 P2.8 P2.14 P2.38 P2.40 P2.42 P2.44 P2.46 P2.48 P2.50 R2.1 R3.2 R10.1 R12.2 U14.5(IN+) U15.5(IN+) U16.5(IN+) U17.5(IN+)
N5: P2.11
N15: C16.2 C75.1 C77.1 C83.1 C85.1 P2.7 U3.4(V-) U14.4(V-) U15.4(V-) U16.4(V-) U17.4(V-)
N21: P2.3
P5: P2.9 R64.1 R65.1
P15: C15.2 C76.1 C78.1 C84.1 C86.1 P2.5 U3.7(V+) U14.8(V+) U15.8(V+) U16.8(V+) U17.8(V+)
P21: P2.1
VDD: P2.13
VREFN: P2.12
VREFP: P2.10
BIAS1: J2.10 P2.43
BIAS2: J2.11 P2.39 R80.2 R81.2 U17.3(IN+)
BIAS2_P: J1.4 R86.1 R87.1
BISA2_N: J1.9 R88.1 R89.1
CTRL: P2.49 R8.2 R78.2 R79.2 U16.3(IN+)
CTRL_N: J1.7 R84.1 R85.1
CTRL_P: J1.2 R82.1 R83.1
ERR: P2.47
EXC_EN: FR6.1 P2.32
EXC_SW: FR4.1 P2.34 R65.8
GAIN0: P2.23
GAIN1: P2.25
GAIN2: P2.27
GAIN3: P2.29
INTEXT: FR8.1 P2.30
LOOP: P2.26
MON1: P2.45 R66.2 R67.2 U14.3(IN+)
MON1_N: J1.6 R72.1 R73.1
MON1_P: J1.1 R70.1 R71.1
MON2: P2.41 R68.2 R69.2 U15.3(IN+)
MON2_N: J1.8 R76.1 R77.1
MON2_P: J1.3 R74.1 R75.1
OK: FR9.1 P2.24
POL: P2.28
RF_ON: FR7.1 P2.31
SLOWCTRL: J2.12 R19.1
SP0: FR1.1 P2.37 R65.5
SP1: FR2.1 P2.36 R65.6
SP2: FR3.1 P2.35 R65.7
VAL0: FR10.1 P2.22 R64.9
VAL1: FR11.1 P2.21 R64.8
VAL2: FR12.1 P2.20 R64.7
VAL3: FR13.1 P2.19 R64.6
VAL4: FR14.1 P2.18 R64.5
VAL5: FR15.1 P2.17 R64.4
VAL6: FR16.1 P2.16 R64.3
VAL7: FR17.1 P2.15 R64.2
VALEN: FR5.1 P2.33 R65.9
NetC6_2: C6.2 J1.10(MH1) J1.11(MH2) R2.2
NetC11_1: C11.1 J2.26(MH1) J2.27(MH2) R3.1
NetC13_1: C13.1 R8.1 R12.1 U3.3(IN+)
NetC79_1: C79.1 R72.2 U14.7(OUT)
NetC79_2: C79.2 R67.1 R73.2 U14.6(IN-)
NetC80_1: C80.1 R76.2 U15.7(OUT)
NetC80_2: C80.2 R69.1 R77.2 U15.6(IN-)
NetC81_1: C81.1 R71.2 U14.1(OUT)
NetC81_2: C81.2 R66.1 R70.2 U14.2(IN-)
NetC82_1: C82.1 R75.2 U15.1(OUT)
NetC82_2: C82.2 R68.1 R74.2 U15.2(IN-)
NetC87_1: C87.1 R84.2 U16.7(OUT)
NetC87_2: C87.2 R79.1 R85.2 U16.6(IN-)
NetC88_1: C88.1 R88.2 U17.7(OUT)
NetC88_2: C88.2 R81.1 R89.2 U17.6(IN-)
NetC89_1: C89.1 R83.2 U16.1(OUT)
NetC89_2: C89.2 R78.1 R82.2 U16.2(IN-)
NetC90_1: C90.1 R87.2 U17.1(OUT)
NetC90_2: C90.2 R80.1 R86.2 U17.2(IN-)
NetFR1_2: FR1.2 J2.1
NetFR2_2: FR2.2 J2.14
NetFR3_2: FR3.2 J2.2
NetFR4_2: FR4.2 J2.15
NetFR5_2: FR5.2 J2.3
NetFR6_2: FR6.2 J2.16
NetFR7_2: FR7.2 J2.4
NetFR8_2: FR8.2 J2.17
NetFR9_2: FR9.2 J2.5
NetFR10_2: FR10.2 J2.18
NetFR11_2: FR11.2 J2.6
NetFR12_2: FR12.2 J2.19
NetFR13_2: FR13.2 J2.7
NetFR14_2: FR14.2 J2.20
NetFR15_2: FR15.2 J2.8
NetFR16_2: FR16.2 J2.21
NetFR17_2: FR17.2 J2.9
NetR10_2: R10.2 R15.1 U3.2(IN-)
NetR15_2: R15.2 R19.2 U3.6(OUT)

Not connected (* = marked no-connect by the designer): J1 5*; R65 2 3 4; U3 1(CMPEN)* 5(NC)* 8(CMPEN)*

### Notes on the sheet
- Remote Controls
- (near J1) DAQ
- RF AM Stabilization Power
- D0900848
- 3
- C
- Daniel Sigg

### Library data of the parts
C6 C11 C15 C16 C75-C78 C83-C86 = ChipCap: as C1 on sheet EOMDriverPower1
C13 = CapFilmAxial: Film Capacitor, axial lead; Part Number: WA2A105F; Tolerance: 1%; Voltage Rating: 50V
C79-C82 C87-C90 = ChipCap: Capacitor, surface mount; Part Number: 311-1105-1-ND; Tolerance: 10%
FR1-FR17 = BLM31PG121SN1: ferrite bead, 120Ohm at 100MHz, 1206; Part Number: 490-1056-1-ND
J1 = DB9F: Receptacle Assembly, 9 Position, Right Angle, .318 Series; Part Number: A32119-ND
J2 = DB25F: Receptacle Assembly, 25 Position, Right Angle, .318 Series; Part Number: A32128-ND
LOGO1#2 = LIGO_logo
P2 = 09 18 150 9421: Flat Cable Connector (IDC), PCB Transition Connector, 2 Rows, Kinked Solder Pin, 50 Contacts; Part Number: A33189-ND
R2 R3 = ChipRes1: as R1 on sheet EOMDriverPower1
R8 = ChipRes1: as R9 on sheet EOMDriverPower1
R10 R12 = ChipRes1: Resistor, surface mount; Tolerance: 0.1%
R15 = ChipRes1: Resistor, surface mount; Part Number: 541-0.0ACT-ND; Tolerance: 0.1%
R19 R71 R72 R75 R76 R83 R84 R87 R88 = ChipRes1: as R22 on sheet EOMDriverPower1
R64 R65 = RES8_BUSROW: Resistor Network, bussed row, 8 resistors; Part Number: 752-091-4.7KPCT-ND; CTS_752-091: 1.27mm spacing, single row; CTS_753_091: 0.64mm spacing, single row
R66-R69 R78-R82 R85 R86 R89 = ChipRes1: Resistor, surface mount; Part Number: P4.99KDACT-ND; Tolerance: 0.1%
R70 R73 R74 R77 = ChipRes1: Resistor, surface mount; Part Number: P49.9KDACT-ND; Tolerance: 0.1%
U3 = OP27GS: as U5 on sheet EOMDriverPower1
U14-U17 = OP285ES: Dual, 9MHz Precision Operational Amplifier; Part Number: AD8672ARZ-ND

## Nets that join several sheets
+5: EOMDriverPower1 (P4.12), EOMDriverPower2 (6 pins)
+15: EOMDriverPower1 (P4.4), EOMDriverPower2 (8 pins)
+18: EOMDriverPower1 (P4.7 TP3.1), EOMDriverPower2 (C54.1 C55.1 D32.1 D33.1)
+21: EOMDriverPower1 (P4.2), EOMDriverPower2 (5 pins)
+24: EOMDriverPower1 (P4.6 TP2.1), EOMDriverPower2 (5 pins)
+24AMP: EOMDriverPower1 (P4.5), EOMDriverPower2 (7 pins)
+VREF: EOMDriverPower1 (TP9.1), EOMDriverPower2 (P10.4)
-5: EOMDriverPower1 (P4.11), EOMDriverPower2 (6 pins)
-15: EOMDriverPower1 (P4.3), EOMDriverPower2 (5 pins)
-18: EOMDriverPower1 (P4.9 TP5.1), EOMDriverPower2 (C39.1 C40.1 D23.2 D24.2)
-21: EOMDriverPower1 (P4.1), EOMDriverPower2 (5 pins)
-24: EOMDriverPower1 (P4.10 TP6.1), EOMDriverPower2 (C38.1 D22.2)
-VREF: EOMDriverPower1 (TP10.1), EOMDriverPower2 (P10.2)
GND: EOMDriverPower1 (48 pins), EOMDriverPower2 (36 pins), EOMDriverPower3 (38 pins)
N5: EOMDriverPower1 (P3.11), EOMDriverPower2 (D20.3 R44.1), EOMDriverPower3 (P2.11)
N15: EOMDriverPower1 (P3.3), EOMDriverPower2 (D19.3 R42.1), EOMDriverPower3 (11 pins)
N21: EOMDriverPower1 (P3.1), EOMDriverPower2 (D18.3 R40.1), EOMDriverPower3 (P2.3)
N24: EOMDriverPower1 (11 pins), EOMDriverPower2 (6 pins)
P5: EOMDriverPower1 (P3.12), EOMDriverPower2 (D28.1 R58.2), EOMDriverPower3 (P2.9 R64.1 R65.1)
P15: EOMDriverPower1 (P3.4), EOMDriverPower2 (D27.1 R56.2), EOMDriverPower3 (11 pins)
P21: EOMDriverPower1 (P3.2), EOMDriverPower2 (D29.1 R54.2), EOMDriverPower3 (P2.1)
P24: EOMDriverPower1 (14 pins), EOMDriverPower2 (8 pins)
P24AMP: EOMDriverPower1 (P3.5), EOMDriverPower2 (D36.1 R63.2)
PGND: EOMDriverPower1 (6 pins), EOMDriverPower2 (35 pins)
VREFN: EOMDriverPower1 (5 pins), EOMDriverPower2 (P9.2 R34.1 R35.1 R36.1), EOMDriverPower3 (P2.12)
VREFP: EOMDriverPower1 (8 pins), EOMDriverPower2 (5 pins), EOMDriverPower3 (P2.10)
OK: EOMDriverPower1 (6 pins), EOMDriverPower3 (FR9.1 P2.24)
